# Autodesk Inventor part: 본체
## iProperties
Company: 한국ATC센터
Created: 2014-01
Part Number: 본체
Document SubType Name: Modeling
Designer: KYOUNG IL JANG
Density: 1 g/cm^3
Material: 기본값
Mass: 657.987 g
Surface Area: 1165.97 cm^2
Volume: 657.987 cm^3
Vendor: CBT Solutions
Author: KYOUNG IL JANG
